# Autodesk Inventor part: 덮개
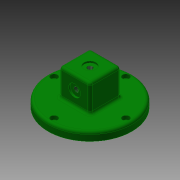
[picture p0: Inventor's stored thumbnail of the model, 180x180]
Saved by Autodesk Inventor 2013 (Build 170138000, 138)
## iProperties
Created: 2017-08
Part Number: 덮개
Material: 알루미늄 6061
Document SubType Name: Modeling
Designer: mduedu
Density: 1 g/cm^3
Author: mduedu
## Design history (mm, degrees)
sketch "스케치1"
  geometry: C1 r 49 at (0, 0); 1 further point
  constraints: 1 centre point, 1 coincident
  dimensions: "d55" = 98 diameter of C1
extrude "돌출1" new body sketch "스케치1" distance "d5" = 10; taper "d6" = 0 deg
sketch "스케치2"
  geometry: L1 (-18, -18)-(18, -18); L2 (18, -18)-(18, 18); L3 (18, 18)-(-18, 18); L4 (-18, 18)-(-18, -18); L5 (-18, -18)-(18, 18); L6 (18, -18)-(-18, 18); 1 further point
  constraints: 12 end point, 2 midpoint, 2 parallel, 2 perpendicular, 1 horizontal
  dimensions: "d7" = 36 distance of L2.end L3.end
extrude "돌출2" join sketch "스케치2" distance "d9" = 32; taper "d10" = 0 deg
sketch "스케치3"
  geometry: C1 r 37 at (0, 0); 1 further point
  constraints: 1 centre point, 1 coincident
  dimensions: "d56" = 74 diameter of C1
extrude "돌출3" join sketch "스케치3" distance "d12" = 7; taper "d13" = 0 deg
sketch "스케치4"
  geometry: C1 r 33 at (0, 0); 1 further point
  constraints: 1 centre point, 1 coincident
  dimensions: "d57" = 66 diameter of C1
extrude "돌출4" cut sketch "스케치4" distance "d16" = 6; taper "d17" = 0 deg
sketch "스케치5"
  geometry: C1 r 9 at (0, 0); 1 further point
  constraints: 1 centre point, 1 coincident
  dimensions: "d18" = 18 diameter of C1
extrude "돌출5" cut sketch "스케치5" distance "d19" = 34; taper "d20" = 0 deg
sketch "스케치6"
  geometry: 2 further points
  constraints: 1 coincident
hole "구멍1" sketch "스케치6" at (0, 0) diameter "d21" = 5.917; stored, may be unused: countersink angle "d25" = 90 deg, drill point angle "d27" = 118 deg; dims "d22" = 6, "d23" = 14, "d24" = 2, "d26" = 8
sketch "스케치7"
  geometry: L1 (-31, -10)-(67, -10) reference; 3 further points
  constraints: 1 midpoint, 1 vertical alignment
  dimensions: "d58" = 26 distance from line of point (18, 16) L1
hole "구멍2" sketch "스케치7" at (18, 16) diameter "d29" = 5.917; stored, may be unused: countersink angle "d33" = 90 deg, drill point angle "d35" = 118 deg; dims "d30" = 6, "d31" = 14, "d32" = 2, "d34" = 8
fillet "모깎기2" dims "d37" = 3
fillet "모깎기3" dims "d38" = 3
fillet "모깎기4" dims "d39" = 3
fillet "모깎기5" dims "d40" = 3
chamfer "모따기1" distance "d41" = 1; stored, may be unused: second distance "d42" = 2, angle "d43" = 45 deg
fillet "모깎기7" dims "d45" = 3
fillet "모깎기8" dims "d46" = 3
sketch "스케치10" dims "d59" = 84
  geometry: 3 further points
  constraints: 2 vertical alignment, 1 coincident, 2 other
hole "구멍4" sketch "스케치10" at (0, 42) diameter "d60" = 4.5; stored, may be unused: countersink angle "d64" = 90 deg, drill point angle "d66" = 118 deg; dims "d61" = 6, "d62" = 8, "d63" = 4.6, "d65" = 8
node "솔리드1"
pattern_circular "원형 패턴1" dims angle "d68" = 360 deg
